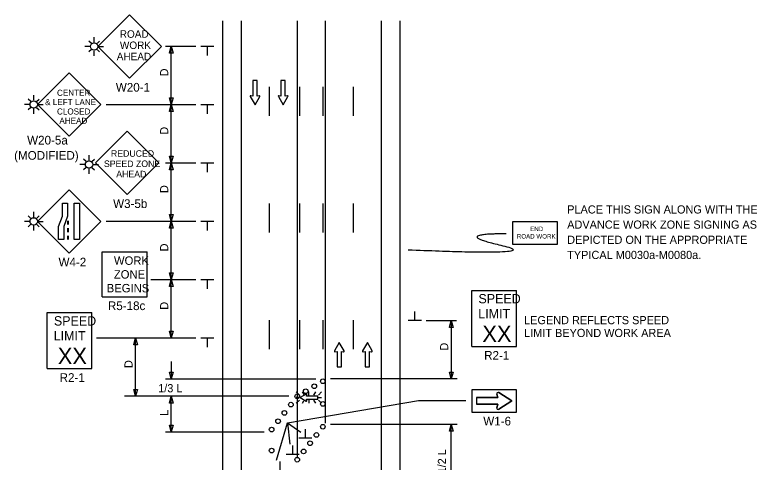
# Model space of a CAD drawing. Extents: x 16738 to 19504, y 5697 to 6916.
# Drawn here: x 16769 to 17406, y 6533 to 6916 of the extents above; entities that cross this region are included whole.
import ezdxf

# ---------------------------------------------------------------- set-up
doc = ezdxf.new("R2010")
doc.units = 0
for name, color, linetype in [('ALI_LEGAL_EX', 7, 'Continuous'), ('MT_SCRATCH_LEVEL_E', 7, 'Continuous'), ('PAVT_EDGE_EX', 7, 'Continuous'), ('TRAFFIC_SIGNS_PR', 7, 'Continuous'), ('TYPICAL_TEXT_DIMEN_PR', 7, 'Continuous')]:
    doc.layers.add(name, color=color, linetype=linetype)

msp = doc.modelspace()

# ---------------------------------------------------------------- linework, layer by layer
at = {"layer": 'ALI_LEGAL_EX'}
for points in [[(16987.43, 6854.77), (16987.43, 6829.77)], [(17013.43, 6854.77), (17013.43, 6829.77)], [(17033.43, 6854.77), (17033.43, 6829.77)], [(17059.43, 6854.77), (17059.43, 6829.77)], [(16987.43, 6754.77), (16987.43, 6729.77)], [(17013.43, 6754.77), (17013.43, 6729.77)], [(17033.43, 6754.77), (17033.43, 6729.77)], [(17059.43, 6754.77), (17059.43, 6729.77)], [(16987.43, 6654.77), (16987.43, 6629.77)], [(17013.43, 6654.77), (17013.43, 6629.77)], [(17033.43, 6654.77), (17033.43, 6629.77)], [(17059.43, 6654.77), (17059.43, 6629.77)]]:
    msp.add_lwpolyline(points, dxfattribs=at)
at = {"layer": 'MT_SCRATCH_LEVEL_E'}
for p, q in [((16977.1, 6860.07), (16973.36, 6860.07)), ((16973.36, 6860.07), (16973.36, 6846.81)), ((16977.1, 6860.07), (16973.36, 6860.07)), ((16973.36, 6860.07), (16973.36, 6846.81)), ((16977.1, 6846.81), (16977.1, 6860.07)), ((16977.1, 6846.81), (16977.1, 6860.07)), ((17001.17, 6860.07), (16997.43, 6860.07)), ((16997.43, 6860.07), (16997.43, 6846.81)), ((17001.17, 6860.07), (16997.43, 6860.07)), ((16997.43, 6860.07), (16997.43, 6846.81)), ((17001.17, 6846.81), (17001.17, 6860.07)), ((17001.17, 6846.81), (17001.17, 6860.07)), ((16971.1, 6846.44), (16975.25, 6839.2)), ((16971.1, 6846.44), (16975.25, 6839.2)), ((16973.36, 6846.81), (16971.58, 6847.12)), ((16973.36, 6846.81), (16971.58, 6847.12)), ((16975.25, 6839.2), (16979.36, 6846.44)), ((16975.25, 6839.2), (16979.36, 6846.44)), ((16978.88, 6847.12), (16977.1, 6846.81)), ((16978.88, 6847.12), (16977.1, 6846.81)), ((16995.18, 6846.44), (16999.32, 6839.2)), ((16995.18, 6846.44), (16999.32, 6839.2)), ((16997.43, 6846.81), (16995.65, 6847.12)), ((16997.43, 6846.81), (16995.65, 6847.12)), ((16999.32, 6839.2), (17003.43, 6846.44)), ((16999.32, 6839.2), (17003.43, 6846.44)), ((17002.95, 6847.12), (17001.17, 6846.81)), ((17002.95, 6847.12), (17001.17, 6846.81)), ((17047.37, 6635.6), (17043.26, 6628.36)), ((17047.37, 6635.6), (17043.26, 6628.36)), ((17051.52, 6628.36), (17047.37, 6635.6)), ((17051.52, 6628.36), (17047.37, 6635.6)), ((17071.54, 6635.6), (17067.43, 6628.36)), ((17071.54, 6635.6), (17067.43, 6628.36)), ((17075.69, 6628.36), (17071.54, 6635.6)), ((17075.69, 6628.36), (17071.54, 6635.6)), ((17043.74, 6627.67), (17045.52, 6627.99)), ((17043.74, 6627.67), (17045.52, 6627.99)), ((17045.52, 6627.99), (17045.52, 6614.73)), ((17045.52, 6627.99), (17045.52, 6614.73)), ((17049.26, 6614.73), (17049.26, 6627.99)), ((17049.26, 6627.99), (17051.04, 6627.67)), ((17049.26, 6614.73), (17049.26, 6627.99)), ((17049.26, 6627.99), (17051.04, 6627.67)), ((17067.91, 6627.67), (17069.69, 6627.99)), ((17067.91, 6627.67), (17069.69, 6627.99)), ((17069.69, 6627.99), (17069.69, 6614.73)), ((17069.69, 6627.99), (17069.69, 6614.73)), ((17073.43, 6614.73), (17073.43, 6627.99)), ((17073.43, 6627.99), (17075.21, 6627.67)), ((17073.43, 6614.73), (17073.43, 6627.99)), ((17073.43, 6627.99), (17075.21, 6627.67)), ((17045.52, 6614.73), (17049.26, 6614.73)), ((17045.52, 6614.73), (17049.26, 6614.73)), ((17069.69, 6614.73), (17073.43, 6614.73)), ((17069.69, 6614.73), (17073.43, 6614.73))]:
    msp.add_line(p, q, dxfattribs=at)
for centre, start, end in [((16971.51, 6846.66), 80.03619, 209.77312), ((16971.51, 6846.66), 80.03619, 209.77312), ((16978.96, 6846.67), 330.42484, 99.96381), ((16978.96, 6846.67), 330.42484, 99.96381), ((16995.59, 6846.66), 80.03619, 209.77312), ((16995.59, 6846.66), 80.03619, 209.77312), ((17003.03, 6846.67), 330.42484, 99.96381), ((17003.03, 6846.67), 330.42484, 99.96381), ((17043.67, 6628.13), 150.42484, 279.96381), ((17043.67, 6628.13), 150.42484, 279.96381), ((17051.11, 6628.13), 260.03619, 29.77312), ((17051.11, 6628.13), 260.03619, 29.77312), ((17067.84, 6628.13), 150.42484, 279.96381), ((17067.84, 6628.13), 150.42484, 279.96381), ((17075.28, 6628.13), 260.03619, 29.77312), ((17075.28, 6628.13), 260.03619, 29.77312)]:
    msp.add_arc(centre, 0.463, start, end, dxfattribs=at)
at = {"layer": 'PAVT_EDGE_EX'}
for p, q in [((16947.43, 6911.29), (16947.43, 6113.54)), ((16963.43, 6911.29), (16963.43, 6113.54)), ((17011.43, 6911.29), (17011.43, 6536.81)), ((17035.43, 6911.29), (17035.43, 6566.36)), ((17083.43, 6911.29), (17083.43, 6113.54)), ((17099.43, 6911.29), (17099.43, 6113.54))]:
    msp.add_line(p, q, dxfattribs=at)
at = {"layer": 'TRAFFIC_SIGNS_PR'}
for p, q in [((16867.66, 6916.43), (16840.48, 6889.24)), ((16894.85, 6889.24), (16867.66, 6916.43)), ((16837.32, 6892.8), (16837.32, 6897.3)), ((16834.17, 6889.24), (16829.33, 6889.24)), ((16834.81, 6891.76), (16832.7, 6893.87)), ((16839.84, 6891.76), (16841.94, 6893.87)), ((16840.48, 6889.24), (16845.36, 6889.24)), ((16840.48, 6889.24), (16867.66, 6862.06)), ((16867.66, 6862.06), (16894.85, 6889.24)), ((16834.81, 6886.73), (16832.7, 6884.62)), ((16837.32, 6881.28), (16837.32, 6885.69)), ((16839.84, 6886.73), (16841.94, 6884.62)), ((16815.73, 6866.81), (16788.55, 6839.62)), ((16842.92, 6839.62), (16815.73, 6866.81)), ((16782.88, 6842.14), (16780.77, 6844.24)), ((16785.39, 6843.18), (16785.39, 6847.68)), ((16787.91, 6842.14), (16790.01, 6844.24)), ((16782.24, 6839.62), (16777.4, 6839.62)), ((16782.88, 6837.11), (16780.77, 6835)), ((16787.91, 6837.11), (16790.01, 6835)), ((16788.55, 6839.62), (16793.43, 6839.62)), ((16788.55, 6839.62), (16815.73, 6812.44)), ((16815.73, 6812.44), (16842.92, 6839.62)), ((16785.39, 6831.66), (16785.39, 6836.07)), ((16865.57, 6816.64), (16838.42, 6789.49)), ((16892.72, 6789.49), (16865.57, 6816.64)), ((16830.32, 6790.68), (16828.21, 6792.79)), ((16832.83, 6791.72), (16832.83, 6796.22)), ((16835.34, 6790.68), (16837.45, 6792.79)), ((16829.68, 6788.17), (16824.84, 6788.17)), ((16835.98, 6788.17), (16840.87, 6788.17)), ((16838.42, 6789.49), (16865.57, 6762.33)), ((16865.57, 6762.33), (16892.72, 6789.49)), ((16830.32, 6785.65), (16828.21, 6783.54)), ((16832.83, 6780.2), (16832.83, 6784.61)), ((16835.34, 6785.65), (16837.45, 6783.55)), ((16815.73, 6766.57), (16788.58, 6739.42)), ((16842.89, 6739.42), (16815.73, 6766.57)), ((16782.88, 6741.96), (16780.77, 6744.07)), ((16785.39, 6743.01), (16785.39, 6747.51)), ((16787.91, 6741.96), (16790.01, 6744.07)), ((16782.24, 6739.45), (16777.4, 6739.45)), ((16782.88, 6736.94), (16780.77, 6734.83)), ((16785.39, 6731.48), (16785.39, 6735.9)), ((16787.91, 6736.94), (16790.01, 6734.83)), ((16788.55, 6739.45), (16793.43, 6739.45)), ((16788.58, 6739.42), (16815.73, 6712.26)), ((16814.49, 6739.91), (16814.49, 6736.71)), ((16814.89, 6739.91), (16814.89, 6736.71)), ((16815.73, 6712.26), (16842.89, 6739.42)), ((16814.49, 6733.51), (16814.49, 6730.31)), ((16814.89, 6733.51), (16814.89, 6730.31)), ((16814.49, 6727.11), (16814.49, 6723.91)), ((16814.89, 6727.11), (16814.89, 6723.91)), ((16844.22, 6674.82), (16844.22, 6713.22)), ((16844.22, 6713.22), (16882.62, 6713.22)), ((16882.62, 6674.82), (16882.62, 6713.22)), ((17161, 6680.31), (17199.4, 6680.31)), ((17161, 6632.31), (17161, 6680.31)), ((17199.4, 6632.31), (17199.4, 6680.31)), ((16844.22, 6674.82), (16882.62, 6674.82)), ((16796.93, 6661.29), (16835.33, 6661.29)), ((16796.93, 6613.29), (16796.93, 6661.29)), ((16835.33, 6613.29), (16835.33, 6661.29)), ((17161, 6632.31), (17199.4, 6632.31)), ((16796.93, 6613.29), (16835.33, 6613.29)), ((17010.52, 6593.2), (17013.34, 6590.39)), ((17017.24, 6591.02), (17015.98, 6593.2)), ((17021.42, 6590.39), (17021.42, 6593.2)), ((17025.56, 6590.39), (17027.19, 6593.2)), ((17029.51, 6590.39), (17032.33, 6593.21)), ((17183.4, 6588.35), (17182.56, 6591.41)), ((17184.24, 6592.65), (17195.4, 6585.55)), ((17013.34, 6588.35), (17010.52, 6588.35)), ((17010.52, 6583.5), (17013.34, 6586.32)), ((17015.95, 6583.5), (17017.16, 6585.59)), ((17021.42, 6586.32), (17021.42, 6583.5)), ((17027.21, 6583.5), (17025.58, 6586.32)), ((17029.51, 6588.35), (17032.33, 6588.35)), ((17029.51, 6586.32), (17032.33, 6583.5)), ((17165, 6588.35), (17183.4, 6588.35)), ((17165, 6588.35), (17165, 6582.75)), ((17183.4, 6582.75), (17165, 6582.75)), ((17182.56, 6579.69), (17183.4, 6582.75)), ((17195.4, 6585.55), (17184.24, 6578.45))]:
    msp.add_line(p, q, dxfattribs=at)
for points in [[(16814.49, 6755.15), (16814.49, 6743.97), (16811.14, 6735.09), (16811.14, 6723.91), (16806.65, 6723.91), (16806.65, 6735.09), (16809.99, 6743.97), (16809.99, 6755.15)], [(16824.62, 6755.15), (16824.62, 6723.91), (16820.13, 6723.91), (16820.13, 6755.15)], [(17196.1, 6719.96), (17234.5, 6719.96), (17234.5, 6739.16), (17196.1, 6739.16)], [(17161, 6575.95), (17199.4, 6575.95), (17199.4, 6595.15), (17161, 6595.15)]]:
    msp.add_lwpolyline(points, close=True, dxfattribs=at)
for points in [[(17019.1, 6591.37), (17013.79, 6588.35), (17019.1, 6585.31)], [(17019.6, 6585.67), (17019.37, 6586.97), (17029.09, 6586.97), (17029.09, 6589.71), (17019.37, 6589.71), (17019.6, 6591.01)], [(17182.56, 6591.41), (17183.4, 6588.35), (17165, 6588.35), (17165, 6582.75), (17183.4, 6582.75), (17182.56, 6579.69)], [(17184.24, 6578.45), (17195.4, 6585.55), (17184.24, 6592.65)]]:
    msp.add_lwpolyline(points, dxfattribs=at)
for centre, radius in [((16837.32, 6889.25), 3.15), ((16785.39, 6839.62), 3.15), ((16832.83, 6788.17), 3.15), ((16785.39, 6739.45), 3.15), ((17033.32, 6602.39), 2), ((17018.66, 6593.78), 2), ((17025.99, 6598.09), 2), ((17011.34, 6589.47), 2), ((17005.92, 6582.34), 2), ((17033.32, 6582.9), 2), ((17000.42, 6575.21), 2), ((16994.93, 6568.08), 2), ((17033.32, 6563.4), 2), ((16989.44, 6560.95), 2), ((16989.44, 6560.95), 2), ((17027.84, 6556.34), 2), ((17022.35, 6549.29), 2), ((16989.44, 6542.95), 2), ((17016.87, 6542.23), 2), ((17011.38, 6535.18), 2)]:
    msp.add_circle(centre, radius, dxfattribs=at)
for centre, radius, start, end in [((17019.26, 6591.07), 0.341, 350.73078, 118.89165), ((17183.64, 6591.71), 1.12, 57.53038, 195.32692), ((17183.64, 6591.71), 1.12, 57.53038, 195.32692), ((17019.26, 6585.61), 0.341, 241.48329, 9.95933), ((17183.64, 6579.4), 1.12, 164.67308, 302.46962), ((17183.64, 6579.4), 1.12, 164.67308, 302.46963)]:
    msp.add_arc(centre, radius, start, end, dxfattribs=at)
msp.add_open_spline([(17190.41, 6728.74), (17143.17, 6728.74), (17228.2, 6709.4), (17106.38, 6714.89)], degree=2, dxfattribs=at)
at = {"layer": 'TYPICAL_TEXT_DIMEN_PR'}
for p, q in [((16898.34, 6889.48), (16924.34, 6889.48)), ((16901.77, 6883.61), (16903.34, 6889.48)), ((16903.34, 6839.48), (16903.34, 6889.48)), ((16903.34, 6889.48), (16904.91, 6883.61)), ((16928.59, 6889.48), (16939.84, 6889.48)), ((16934.21, 6889.48), (16934.21, 6881.69)), ((16903.34, 6883.61), (16901.77, 6883.61)), ((16904.91, 6883.61), (16903.34, 6883.61)), ((16903.34, 6839.48), (16901.77, 6845.34)), ((16901.77, 6845.34), (16903.34, 6845.34)), ((16903.34, 6845.34), (16904.91, 6845.34)), ((16904.91, 6845.34), (16903.34, 6839.48)), ((16847.54, 6839.48), (16924.34, 6839.48)), ((16898.34, 6839.48), (16924.34, 6839.48)), ((16901.77, 6833.61), (16903.34, 6839.48)), ((16903.34, 6789.48), (16903.34, 6839.48)), ((16903.34, 6839.48), (16904.91, 6833.61)), ((16928.59, 6839.48), (16939.84, 6839.48)), ((16934.21, 6839.48), (16934.21, 6831.69)), ((16903.34, 6833.61), (16901.77, 6833.61)), ((16904.91, 6833.61), (16903.34, 6833.61)), ((16903.34, 6789.48), (16901.77, 6795.34)), ((16901.77, 6795.34), (16903.34, 6795.34)), ((16903.34, 6795.34), (16904.91, 6795.34)), ((16904.91, 6795.34), (16903.34, 6789.48)), ((16898.34, 6789.48), (16924.34, 6789.48)), ((16898.34, 6789.48), (16924.34, 6789.48)), ((16901.77, 6783.61), (16903.34, 6789.48)), ((16903.34, 6789.48), (16904.91, 6783.61)), ((16903.34, 6739.48), (16903.34, 6789.48)), ((16928.59, 6789.48), (16939.84, 6789.48)), ((16934.21, 6789.48), (16934.21, 6781.69)), ((16903.34, 6783.61), (16901.77, 6783.61)), ((16904.91, 6783.61), (16903.34, 6783.61)), ((16903.34, 6739.48), (16901.77, 6745.34)), ((16901.77, 6745.34), (16903.34, 6745.34)), ((16903.34, 6745.34), (16904.91, 6745.34)), ((16904.91, 6745.34), (16903.34, 6739.48)), ((16847.54, 6739.48), (16924.34, 6739.48)), ((16901.77, 6733.61), (16903.34, 6739.48)), ((16903.34, 6739.48), (16904.91, 6733.61)), ((16903.34, 6689.48), (16903.34, 6739.48)), ((16928.59, 6739.48), (16939.84, 6739.48)), ((16934.21, 6739.48), (16934.21, 6731.69)), ((16903.34, 6733.61), (16901.77, 6733.61)), ((16904.91, 6733.61), (16903.34, 6733.61)), ((16903.34, 6689.48), (16901.77, 6695.34)), ((16901.77, 6695.34), (16903.34, 6695.34)), ((16903.34, 6695.34), (16904.91, 6695.34)), ((16904.91, 6695.34), (16903.34, 6689.48)), ((16885.94, 6689.48), (16924.34, 6689.48)), ((16901.77, 6683.61), (16903.34, 6689.48)), ((16903.34, 6639.48), (16903.34, 6689.48)), ((16903.34, 6689.48), (16904.91, 6683.61)), ((16928.59, 6689.48), (16939.84, 6689.48)), ((16934.21, 6689.48), (16934.21, 6681.69)), ((16903.34, 6683.61), (16901.77, 6683.61)), ((16904.91, 6683.61), (16903.34, 6683.61)), ((17112.19, 6654.4), (17112.19, 6662.18)), ((17117.82, 6654.4), (17106.57, 6654.4)), ((17122.07, 6654.4), (17148.07, 6654.4)), ((17141.86, 6648.53), (17143.43, 6654.4)), ((17143.43, 6654.4), (17143.43, 6604.4)), ((17143.43, 6654.4), (17145, 6648.53)), ((17143.43, 6648.53), (17141.86, 6648.53)), ((17145, 6648.53), (17143.43, 6648.53)), ((16839.19, 6639.48), (16924.34, 6639.48)), ((16871.19, 6633.61), (16872.76, 6639.48)), ((16872.76, 6639.48), (16874.33, 6633.61)), ((16872.76, 6589.48), (16872.76, 6639.48)), ((16903.34, 6639.48), (16901.77, 6645.34)), ((16901.77, 6645.34), (16903.34, 6645.34)), ((16903.34, 6645.34), (16904.91, 6645.34)), ((16904.91, 6645.34), (16903.34, 6639.48)), ((16928.59, 6639.48), (16939.84, 6639.48)), ((16934.21, 6639.48), (16934.21, 6631.69)), ((16872.76, 6633.61), (16871.19, 6633.61)), ((16874.33, 6633.61), (16872.76, 6633.61)), ((16903.34, 6619.32), (16903.34, 6604.4)), ((16903.34, 6604.4), (16901.77, 6610.26)), ((16901.77, 6610.26), (16903.34, 6610.26)), ((16903.34, 6610.26), (16904.91, 6610.26)), ((16904.91, 6610.26), (16903.34, 6604.4)), ((17143.43, 6604.4), (17141.86, 6610.26)), ((17141.86, 6610.26), (17143.43, 6610.26)), ((17143.43, 6610.26), (17145, 6610.26)), ((17145, 6610.26), (17143.43, 6604.4)), ((16898.34, 6604.4), (17027.47, 6604.4)), ((17148.43, 6604.4), (17039.85, 6604.4)), ((16872.76, 6589.48), (16871.19, 6595.34)), ((16871.19, 6595.34), (16872.76, 6595.34)), ((16872.76, 6595.34), (16874.33, 6595.34)), ((16874.33, 6595.34), (16872.76, 6589.48)), ((17004.25, 6589.48), (16863.24, 6589.48)), ((17004.25, 6589.48), (16872.76, 6589.48)), ((16901.77, 6583.61), (16903.34, 6589.48)), ((16903.34, 6558.94), (16903.34, 6589.48)), ((16903.34, 6589.48), (16904.91, 6583.61)), ((16903.34, 6583.61), (16901.77, 6583.61)), ((16904.91, 6583.61), (16903.34, 6583.61)), ((17003.11, 6566.74), (17115.49, 6585.86)), ((17115.49, 6585.86), (17155.95, 6585.86)), ((16903.34, 6558.94), (16901.77, 6564.8)), ((16901.77, 6564.8), (16903.34, 6564.8)), ((16903.34, 6564.8), (16904.91, 6564.8)), ((16904.91, 6564.8), (16903.34, 6558.94)), ((16993.63, 6534.8), (17003.11, 6566.74)), ((17003.11, 6566.74), (17005.01, 6548.49)), ((17003.11, 6566.74), (17014.49, 6558.76)), ((17148.43, 6565.4), (17039.85, 6565.4)), ((17141.86, 6559.54), (17143.43, 6565.4)), ((17143.43, 6506.95), (17143.43, 6565.4)), ((17143.43, 6565.4), (17145, 6559.54)), ((16898.34, 6558.94), (16983.16, 6558.94)), ((17018.34, 6553.59), (17018.34, 6561.38)), ((17143.43, 6559.54), (17141.86, 6559.54)), ((17145, 6559.54), (17143.43, 6559.54)), ((17023.97, 6553.59), (17012.72, 6553.59)), ((17007.51, 6539.66), (17007.51, 6547.45)), ((17013.14, 6539.66), (17001.89, 6539.66)), ((16996.69, 6525.74), (16996.69, 6533.52))]:
    msp.add_line(p, q, dxfattribs=at)

# ---------------------------------------------------------------- texts
at = {"layer": 'TRAFFIC_SIGNS_PR'}
for s, height, p in [('ROAD', 6.408, (16859.19, 6896.79)), ('WORK', 6.408, (16859.3, 6887.18)), ('AHEAD', 6.408, (16856.61, 6877.57)), ('W20-1', 7.449, (16855.82, 6850.61)), ('CENTER', 5.206, (16805.36, 6847.04)), ('& LEFT LANE', 5.2065, (16795.21, 6839.03)), ('CLOSED', 5.206, (16805.36, 6831.02)), ('AHEAD', 5.206, (16807.39, 6823.01)), ('W20-5a', 7.449, (16779.76, 6805.31)), ('(MODIFIED)', 7.449, (16768.6, 6792.25)), ('REDUCED', 5.6, (16851.63, 6794.8)), ('SPEED ZONE', 5.6, (16845.62, 6786)), ('AHEAD', 5.6, (16856.18, 6777.2)), ('W3-5b', 7.44, (16853.52, 6750.9)), ('PLACE THIS SIGN ALONG WITH THE', 7, (17242.88, 6746.16)), ('ADVANCE WORK ZONE SIGNING AS', 7, (17242.88, 6733.16)), ('ROAD WORK', 3.831, (17199.71, 6724.71)), ('END', 3.831, (17211.1, 6731.09)), ('DEPICTED ON THE APPROPRIATE', 7, (17242.88, 6720.16)), ('WORK', 7.217, (16854.21, 6702.19)), ('TYPICAL M0030a-M0080a.', 7, (17242.88, 6707.16)), ('W4-2', 7.44, (16806.69, 6700.82)), ('ZONE', 7.217, (16854.1, 6690.38)), ('BEGINS', 7.217, (16848.02, 6678.57)), ('SPEED', 8, (17166.77, 6669.17)), ('R5-18c', 7.44, (16849.03, 6663.39)), ('LIMIT', 8, (17166.61, 6656.37)), ('SPEED', 8, (16802.7, 6650.15)), ('XX', 14.031, (17170.12, 6636.06)), ('LIMIT', 8, (16802.54, 6637.35)), ('XX', 14.031, (16806.04, 6617.05)), ('R2-1', 7.44, (17171.68, 6620.87)), ('R2-1', 7.44, (16807.61, 6601.85)), ('W1-6', 7.44, (17170.94, 6564.51))]:
    msp.add_text(s, height=height, dxfattribs=at).set_placement(p)
at = {"layer": 'TYPICAL_TEXT_DIMEN_PR'}
for s, p in [('D', (16900.78, 6863.69)), ('D', (16900.78, 6813.69)), ('D', (16900.78, 6763.69)), ('D', (16900.78, 6713.69)), ('D', (16900.78, 6663.69)), ('D', (17140.88, 6628.62)), ('D', (16870.2, 6613.69)), ('L', (16900.78, 6572.81)), ('1/2 L', (17138.98, 6523.36))]:
    msp.add_text(s, height=7, rotation=90, dxfattribs=at).set_placement(p)
for s, p in [('LEGEND REFLECTS SPEED', (17205.94, 6651.29)), ('LIMIT BEYOND WORK AREA', (17205.94, 6640.29)), ('1/3 L', (16892.12, 6592.93))]:
    msp.add_text(s, height=7, dxfattribs=at).set_placement(p)

doc.saveas('drawing.dxf')
